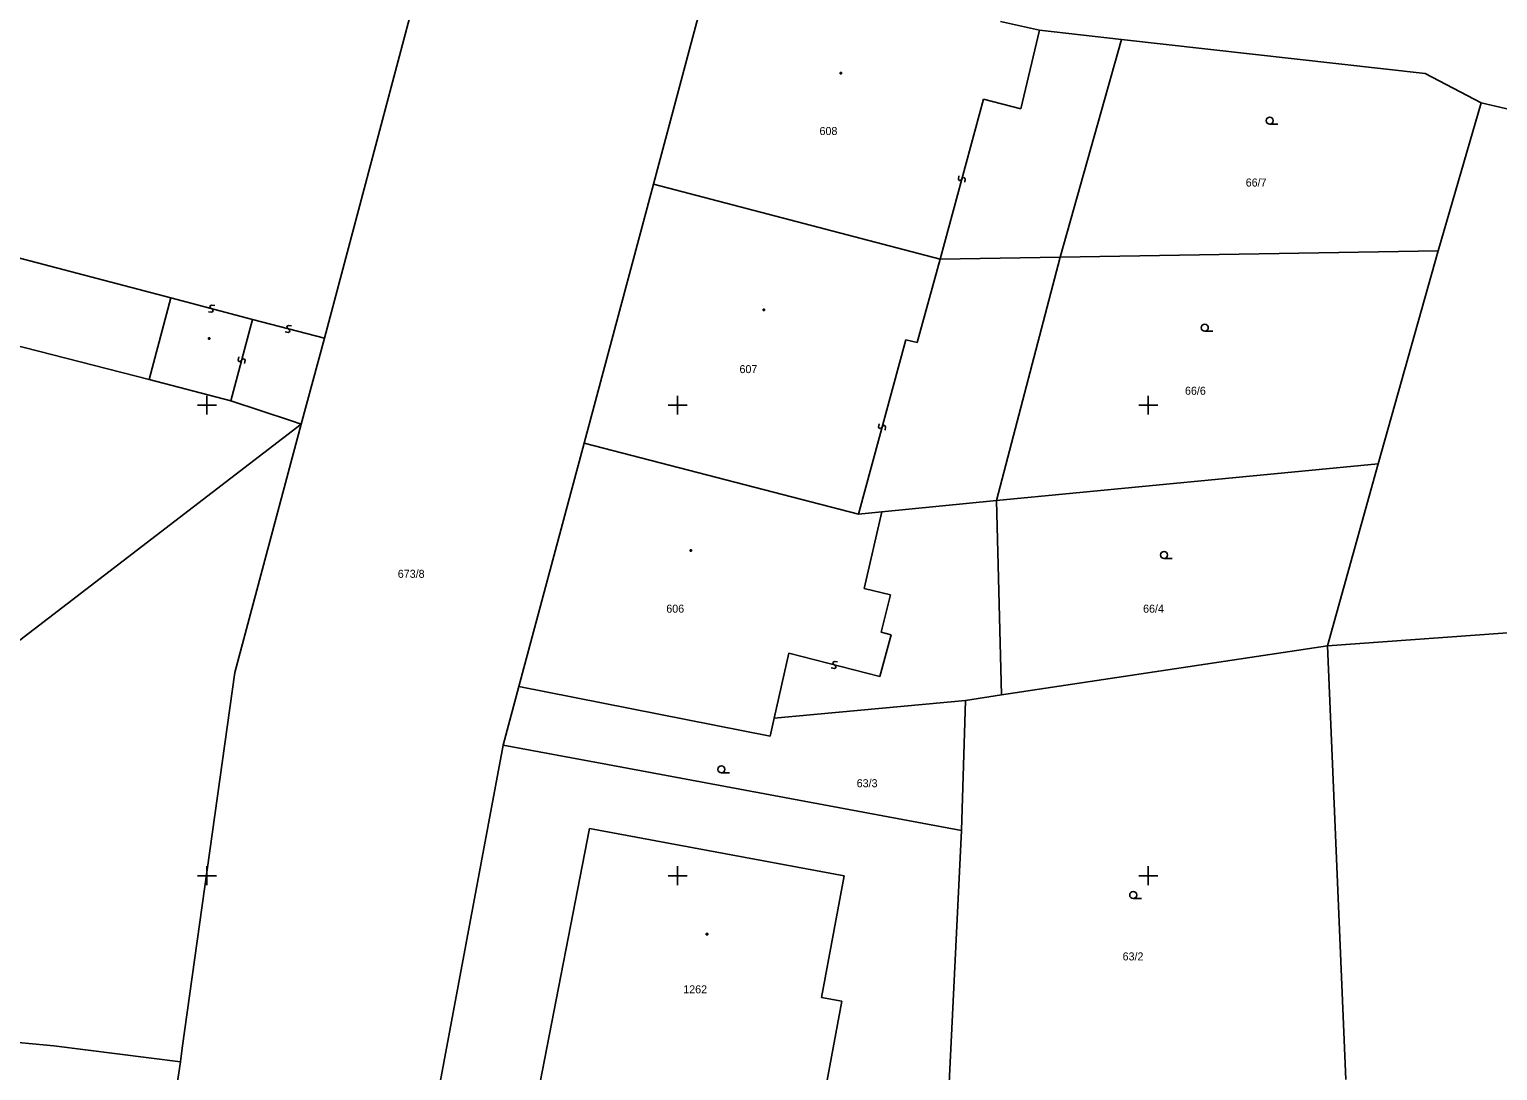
# Model space of a CAD drawing. Extents: x -492811 to -492366, y -1127107 to -1126748.
# Drawn here: x -492547.5 to -492485.2, y -1126888.3 to -1126844 of the extents above; entities that cross this region are included whole.
import ezdxf

# ---------------------------------------------------------------- set-up
doc = ezdxf.new("R2010")
doc.units = 0
doc.layers.add('katastrální mapa', color=7, linetype='Continuous')
doc.layers.add('síť', color=7, linetype='Continuous')

msp = doc.modelspace()

# ---------------------------------------------------------------- linework, layer by layer
at = {"layer": 'katastrální mapa'}
for p, q in [((-492535.01, -1126857.16), (-492530.61, -1126840.63)), ((-492521.03, -1126850.61), (-492518.73, -1126842.01)), ((-492506.28, -1126843.69), (-492504.62, -1126844.07)), ((-492505.41, -1126847.41), (-492504.62, -1126844.07)), ((-492504.62, -1126844.07), (-492501.14, -1126844.46)), ((-492503.75, -1126853.71), (-492501.14, -1126844.46)), ((-492501.14, -1126844.46), (-492488.24, -1126845.91)), ((-492513.09, -1126845.86), (-492513.03, -1126845.86)), ((-492513.09, -1126845.92), (-492513.09, -1126845.86)), ((-492513.03, -1126845.92), (-492513.09, -1126845.92)), ((-492513.03, -1126845.86), (-492513.03, -1126845.92)), ((-492488.24, -1126845.91), (-492485.85, -1126847.15)), ((-492508.85, -1126853.79), (-492507, -1126847)), ((-492507, -1126847), (-492505.41, -1126847.41)), ((-492487.68, -1126853.44), (-492485.85, -1126847.15)), ((-492485.85, -1126847.15), (-492483.79, -1126847.63)), ((-492494.84, -1126848.06), (-492494.49, -1126848.06)), ((-492566.27, -1126848.94), (-492541.54, -1126855.44)), ((-492523.97, -1126861.61), (-492521.03, -1126850.61)), ((-492521.03, -1126850.61), (-492508.85, -1126853.79)), ((-492508.05, -1126850.26), (-492508.07, -1126850.4)), ((-492508.07, -1126850.4), (-492508.04, -1126850.45)), ((-492508.04, -1126850.45), (-492508, -1126850.46)), ((-492508, -1126850.46), (-492507.95, -1126850.43)), ((-492507.95, -1126850.43), (-492507.9, -1126850.36)), ((-492507.9, -1126850.36), (-492507.85, -1126850.33)), ((-492507.85, -1126850.33), (-492507.81, -1126850.34)), ((-492507.81, -1126850.34), (-492507.78, -1126850.39)), ((-492507.78, -1126850.39), (-492507.8, -1126850.53)), ((-492568.28, -1126852.33), (-492542.45, -1126858.91)), ((-492509.82, -1126857.34), (-492508.85, -1126853.79)), ((-492508.85, -1126853.79), (-492503.75, -1126853.71)), ((-492506.45, -1126864.06), (-492503.75, -1126853.71)), ((-492503.75, -1126853.71), (-492487.68, -1126853.44)), ((-492490.23, -1126862.49), (-492487.68, -1126853.44)), ((-492542.45, -1126858.91), (-492541.54, -1126855.44)), ((-492541.54, -1126855.44), (-492538.07, -1126856.36)), ((-492539.8, -1126856.05), (-492539.94, -1126856.03)), ((-492539.86, -1126855.78), (-492539.87, -1126855.82)), ((-492539.87, -1126855.82), (-492539.84, -1126855.87)), ((-492539.81, -1126855.75), (-492539.86, -1126855.78)), ((-492539.84, -1126855.87), (-492539.77, -1126855.93)), ((-492539.67, -1126855.77), (-492539.81, -1126855.75)), ((-492539.75, -1126856.02), (-492539.8, -1126856.05)), ((-492539.77, -1126855.93), (-492539.74, -1126855.98)), ((-492539.74, -1126855.98), (-492539.75, -1126856.02)), ((-492538.98, -1126859.82), (-492538.07, -1126856.36)), ((-492538.07, -1126856.36), (-492535.01, -1126857.16)), ((-492516.37, -1126855.92), (-492516.31, -1126855.92)), ((-492516.37, -1126855.98), (-492516.37, -1126855.92)), ((-492516.31, -1126855.98), (-492516.37, -1126855.98)), ((-492516.31, -1126855.92), (-492516.31, -1126855.98)), ((-492536.54, -1126856.91), (-492536.68, -1126856.89)), ((-492536.59, -1126856.64), (-492536.6, -1126856.68)), ((-492536.6, -1126856.68), (-492536.57, -1126856.73)), ((-492536.54, -1126856.61), (-492536.59, -1126856.64)), ((-492536.57, -1126856.73), (-492536.51, -1126856.79)), ((-492536.4, -1126856.63), (-492536.54, -1126856.61)), ((-492536.49, -1126856.88), (-492536.54, -1126856.91)), ((-492536.51, -1126856.79), (-492536.48, -1126856.84)), ((-492536.48, -1126856.84), (-492536.49, -1126856.88)), ((-492497.6, -1126856.86), (-492497.25, -1126856.86)), ((-492539.94, -1126857.14), (-492539.88, -1126857.14)), ((-492539.94, -1126857.2), (-492539.94, -1126857.14)), ((-492539.88, -1126857.2), (-492539.94, -1126857.2)), ((-492539.88, -1126857.14), (-492539.88, -1126857.2)), ((-492535.99, -1126860.81), (-492535.01, -1126857.16)), ((-492512.32, -1126864.63), (-492510.3, -1126857.22)), ((-492510.3, -1126857.22), (-492509.82, -1126857.34)), ((-492538.65, -1126857.95), (-492538.67, -1126858.09)), ((-492538.67, -1126858.09), (-492538.64, -1126858.14)), ((-492538.64, -1126858.14), (-492538.6, -1126858.15)), ((-492538.6, -1126858.15), (-492538.55, -1126858.12)), ((-492538.55, -1126858.12), (-492538.5, -1126858.06)), ((-492538.5, -1126858.06), (-492538.45, -1126858.03)), ((-492538.45, -1126858.03), (-492538.41, -1126858.04)), ((-492538.41, -1126858.04), (-492538.38, -1126858.09)), ((-492538.38, -1126858.09), (-492538.4, -1126858.23)), ((-492542.45, -1126858.91), (-492538.98, -1126859.82)), ((-492538.98, -1126859.82), (-492536.41, -1126860.67)), ((-492536.41, -1126860.67), (-492535.99, -1126860.81)), ((-492535.99, -1126860.81), (-492566.98, -1126884.57)), ((-492538.82, -1126871.37), (-492535.99, -1126860.81)), ((-492511.44, -1126860.79), (-492511.46, -1126860.93)), ((-492511.46, -1126860.93), (-492511.43, -1126860.98)), ((-492511.43, -1126860.98), (-492511.39, -1126860.99)), ((-492511.39, -1126860.99), (-492511.34, -1126860.96)), ((-492511.34, -1126860.96), (-492511.28, -1126860.89)), ((-492511.28, -1126860.89), (-492511.23, -1126860.86)), ((-492511.23, -1126860.86), (-492511.19, -1126860.87)), ((-492511.19, -1126860.87), (-492511.16, -1126860.92)), ((-492511.16, -1126860.92), (-492511.18, -1126861.06)), ((-492526.74, -1126871.96), (-492523.97, -1126861.61)), ((-492523.97, -1126861.61), (-492512.32, -1126864.63)), ((-492506.45, -1126864.06), (-492490.23, -1126862.49)), ((-492492.39, -1126870.23), (-492490.23, -1126862.49)), ((-492511.32, -1126864.53), (-492506.45, -1126864.06)), ((-492506.45, -1126864.06), (-492506.23, -1126872.32)), ((-492512.32, -1126864.63), (-492511.32, -1126864.53)), ((-492512.07, -1126867.79), (-492511.32, -1126864.53)), ((-492519.47, -1126866.15), (-492519.41, -1126866.15)), ((-492519.47, -1126866.21), (-492519.47, -1126866.15)), ((-492519.41, -1126866.21), (-492519.47, -1126866.21)), ((-492519.41, -1126866.15), (-492519.41, -1126866.21)), ((-492499.33, -1126866.52), (-492498.98, -1126866.52)), ((-492512.07, -1126867.79), (-492510.95, -1126868.07)), ((-492511.35, -1126869.65), (-492510.95, -1126868.07)), ((-492492.39, -1126870.23), (-492478.79, -1126869.25)), ((-492511.4, -1126871.54), (-492510.93, -1126869.76)), ((-492511.35, -1126869.65), (-492510.93, -1126869.76)), ((-492515.89, -1126873.31), (-492515.27, -1126870.54)), ((-492515.27, -1126870.54), (-492511.4, -1126871.54)), ((-492506.23, -1126872.32), (-492492.39, -1126870.23)), ((-492492.39, -1126870.23), (-492491.61, -1126888.66)), ((-492513.33, -1126871.19), (-492513.47, -1126871.17)), ((-492513.39, -1126870.92), (-492513.4, -1126870.96)), ((-492513.4, -1126870.96), (-492513.37, -1126871.01)), ((-492513.34, -1126870.89), (-492513.39, -1126870.92)), ((-492513.37, -1126871.01), (-492513.3, -1126871.07)), ((-492513.2, -1126870.91), (-492513.34, -1126870.89)), ((-492513.28, -1126871.16), (-492513.33, -1126871.19)), ((-492513.3, -1126871.07), (-492513.27, -1126871.12)), ((-492513.27, -1126871.12), (-492513.28, -1126871.16)), ((-492541.05, -1126887.33), (-492538.82, -1126871.37)), ((-492527.41, -1126874.45), (-492526.74, -1126871.96)), ((-492526.74, -1126871.96), (-492516.06, -1126874.07)), ((-492515.89, -1126873.31), (-492507.76, -1126872.55)), ((-492507.93, -1126878.08), (-492507.76, -1126872.55)), ((-492507.76, -1126872.55), (-492506.23, -1126872.32)), ((-492516.06, -1126874.07), (-492515.89, -1126873.31)), ((-492531.04, -1126893.89), (-492527.41, -1126874.45)), ((-492527.41, -1126874.45), (-492522.98, -1126875.28)), ((-492522.98, -1126875.28), (-492507.93, -1126878.08)), ((-492518.14, -1126875.63), (-492517.79, -1126875.63)), ((-492525.85, -1126888.84), (-492523.74, -1126878)), ((-492523.74, -1126878), (-492512.92, -1126880.01)), ((-492508.65, -1126892.62), (-492507.93, -1126878.08)), ((-492513.88, -1126885.17), (-492512.92, -1126880.01)), ((-492500.64, -1126880.97), (-492500.29, -1126880.97)), ((-492518.78, -1126882.45), (-492518.72, -1126882.45)), ((-492518.78, -1126882.51), (-492518.78, -1126882.45)), ((-492518.72, -1126882.51), (-492518.78, -1126882.51)), ((-492518.72, -1126882.45), (-492518.72, -1126882.51)), ((-492514.07, -1126890.94), (-492513.02, -1126885.33)), ((-492513.88, -1126885.17), (-492513.02, -1126885.33)), ((-492546.51, -1126887.23), (-492553.78, -1126886.56)), ((-492541.13, -1126887.91), (-492546.51, -1126887.23)), ((-492541.05, -1126887.33), (-492541.13, -1126887.91)), ((-492541.13, -1126887.91), (-492545.98, -1126921.47))]:
    msp.add_line(p, q, dxfattribs=at)
for centre in [(-492494.84, -1126847.91), (-492497.6, -1126856.71), (-492499.33, -1126866.37), (-492518.14, -1126875.48), (-492500.64, -1126880.82)]:
    msp.add_circle(centre, 0.15, dxfattribs=at)
at = {"layer": 'síť'}
for p, q in [((-492540.4, -1126860), (-492539.6, -1126860)), ((-492540, -1126859.6), (-492540, -1126860.4)), ((-492520.4, -1126860), (-492519.6, -1126860)), ((-492520, -1126859.6), (-492520, -1126860.4)), ((-492500.4, -1126860), (-492499.6, -1126860)), ((-492500, -1126859.6), (-492500, -1126860.4)), ((-492540.4, -1126880), (-492539.6, -1126880)), ((-492540, -1126879.6), (-492540, -1126880.4)), ((-492520.4, -1126880), (-492519.6, -1126880)), ((-492520, -1126879.6), (-492520, -1126880.4)), ((-492500.4, -1126880), (-492499.6, -1126880)), ((-492500, -1126879.6), (-492500, -1126880.4))]:
    msp.add_line(p, q, dxfattribs=at)

# ---------------------------------------------------------------- texts
at = {"layer": 'katastrální mapa'}
for s, p in [('608', (-492513.97, -1126848.52)), ('66/7', (-492495.86, -1126850.71)), ('607', (-492517.37, -1126858.64)), ('66/6', (-492498.44, -1126859.56)), ('673/8', (-492531.89, -1126867.34)), ('606', (-492520.48, -1126868.82)), ('66/4', (-492500.22, -1126868.82)), ('63/3', (-492512.39, -1126876.24)), ('63/2', (-492501.09, -1126883.6)), ('1262', (-492519.76, -1126885))]:
    msp.add_text(s, height=0.34, dxfattribs=at).set_placement(p)

doc.saveas('drawing.dxf')
